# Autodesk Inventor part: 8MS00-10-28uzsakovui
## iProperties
Created: 2009-08
Part Number: 8MS00-10-28uzsakovui
Document SubType Name: Modeling
Designer: Darius
Author: Darius
Translation Standard: STEP AP203
File Name: 8MS00-10-28.STEP
Preprocessor: SolidWorks 2003240
Postprocessor: Build: 272, Release: 10 SP3a - Date: Thu 12/15/2005
Sent Units: MILLIMETERS
Uncertainty: 1e-05
